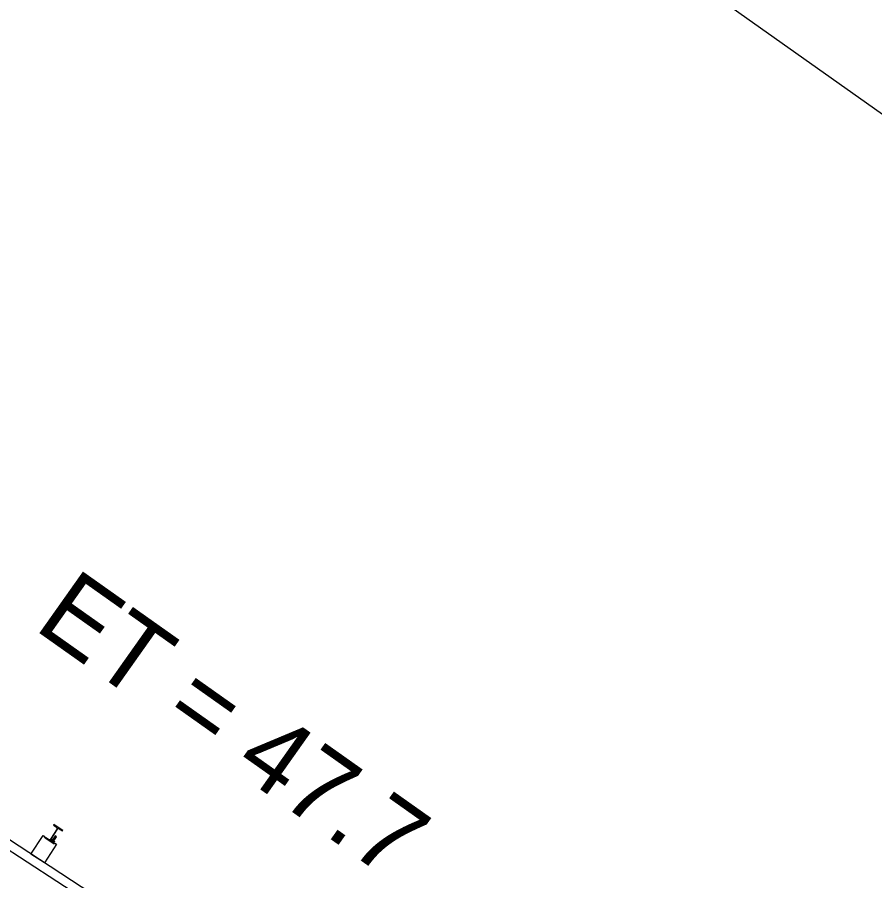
# Model space of a CAD drawing. Extents: x 16457860 to 16462445, y 6896068 to 6900243.
# Drawn here: x 16462375.6 to 16462402.25, y 6897966.79 to 6897993.62 of the extents above; entities that cross this region are included whole.
import ezdxf

# ---------------------------------------------------------------- set-up
doc = ezdxf.new("R2010")
doc.units = 0
for name, color, linetype in [('Draft_DNC', 7, 'Continuous'), ('dsnStdLineWork', 7, 'Continuous'), ('dsnStdShading', 7, 'Continuous')]:
    doc.layers.add(name, color=color, linetype=linetype)

msp = doc.modelspace()

# ---------------------------------------------------------------- linework, layer by layer
at = {"layer": 'Draft_DNC'}
msp.add_lwpolyline([(16462202.578, 6898132.041), (16462444.858, 6897960.634), (16462399.398, 6897896.379), (16462157.118, 6898067.786)], close=True, dxfattribs=at)
at = {"layer": 'dsnStdLineWork'}
for p, q in [((16462392.448, 6897956.957), (16462357.89, 6897979.389)), ((16462392.3, 6897956.73), (16462357.742, 6897979.162)), ((16462376.738, 6897968.531), (16462376.729, 6897968.518)), ((16462376.729, 6897968.518), (16462376.828, 6897968.454)), ((16462377.018, 6897968.35), (16462376.738, 6897968.531)), ((16462376.031, 6897967.614), (16462376.41, 6897968.198)), ((16462376.41, 6897968.198), (16462376.462, 6897968.164)), ((16462376.84, 6897968.397), (16462376.636, 6897968.082)), ((16462376.649, 6897968.074), (16462376.853, 6897968.388)), ((16462376.778, 6897968.182), (16462376.696, 6897968.055)), ((16462376.822, 6897968.154), (16462376.778, 6897968.182)), ((16462376.911, 6897968.4), (16462377.009, 6897968.337)), ((16462377.009, 6897968.337), (16462377.018, 6897968.35)), ((16462376.445, 6897968.137), (16462376.462, 6897968.164)), ((16462376.76, 6897967.933), (16462376.445, 6897968.137)), ((16462376.829, 6897967.926), (16462376.45, 6897967.342)), ((16462376.48, 6897968.134), (16462376.471, 6897968.12)), ((16462376.471, 6897968.12), (16462376.751, 6897967.939)), ((16462376.578, 6897968.07), (16462376.48, 6897968.134)), ((16462376.644, 6897968.038), (16462376.665, 6897968.069)), ((16462376.759, 6897967.952), (16462376.661, 6897968.016)), ((16462376.674, 6897968.069), (16462376.665, 6897968.069)), ((16462376.667, 6897968.018), (16462376.69, 6897968.053)), ((16462376.674, 6897968.069), (16462376.756, 6897968.017)), ((16462376.718, 6897967.986), (16462376.74, 6897968.02)), ((16462376.733, 6897967.969), (16462376.743, 6897967.969)), ((16462376.74, 6897968.027), (16462376.822, 6897968.154)), ((16462376.743, 6897967.969), (16462376.765, 6897968.004)), ((16462376.751, 6897967.939), (16462376.759, 6897967.952)), ((16462376.756, 6897968.017), (16462376.761, 6897968.013)), ((16462376.777, 6897967.96), (16462376.76, 6897967.933)), ((16462376.765, 6897968.004), (16462376.761, 6897968.013)), ((16462376.777, 6897967.96), (16462376.829, 6897967.926)), ((16462376.45, 6897967.342), (16462376.031, 6897967.614))]:
    msp.add_line(p, q, dxfattribs=at)
for centre, start, end in [((16462376.805, 6897968.419), 327.0057, 57.0148), ((16462376.888, 6897968.365), 57.0196, 147.0086), ((16462376.601, 6897968.105), 237.0196, 327.0086), ((16462376.684, 6897968.051), 147.0057, 237.0148)]:
    msp.add_arc(centre, 0.0417, start, end, dxfattribs=at)
for points in [[(16462376.656, 6897968.02), (16462376.657, 6897968.02), (16462376.661, 6897968.018), (16462376.665, 6897968.018), (16462376.667, 6897968.018)], [(16462376.69, 6897968.053), (16462376.688, 6897968.056), (16462376.686, 6897968.061), (16462376.68, 6897968.066), (16462376.672, 6897968.069), (16462376.667, 6897968.069), (16462376.665, 6897968.069)], [(16462376.667, 6897968.018), (16462376.671, 6897968.014), (16462376.678, 6897968.006), (16462376.691, 6897967.996), (16462376.704, 6897967.99), (16462376.713, 6897967.987), (16462376.718, 6897967.986)], [(16462376.74, 6897968.02), (16462376.737, 6897968.024), (16462376.729, 6897968.033), (16462376.717, 6897968.042), (16462376.703, 6897968.049), (16462376.694, 6897968.052), (16462376.69, 6897968.053)], [(16462376.718, 6897967.986), (16462376.718, 6897967.984), (16462376.72, 6897967.98), (16462376.724, 6897967.975), (16462376.731, 6897967.971), (16462376.737, 6897967.969), (16462376.741, 6897967.969), (16462376.743, 6897967.969)], [(16462376.765, 6897968.004), (16462376.765, 6897968.006), (16462376.763, 6897968.009), (16462376.759, 6897968.014), (16462376.753, 6897968.019), (16462376.746, 6897968.02), (16462376.742, 6897968.02), (16462376.74, 6897968.02)]]:
    msp.add_open_spline(points, degree=3, dxfattribs=at)
at = {"layer": 'dsnStdShading'}
for p, q in [((16462376.738, 6897968.531), (16462376.729, 6897968.518)), ((16462376.738, 6897968.531), (16462376.729, 6897968.518)), ((16462376.729, 6897968.518), (16462376.828, 6897968.454)), ((16462376.729, 6897968.518), (16462376.828, 6897968.454)), ((16462377.018, 6897968.35), (16462376.738, 6897968.531)), ((16462377.018, 6897968.35), (16462376.738, 6897968.531)), ((16462376.031, 6897967.614), (16462376.41, 6897968.198)), ((16462376.41, 6897968.198), (16462376.462, 6897968.164)), ((16462376.84, 6897968.397), (16462376.636, 6897968.082)), ((16462376.84, 6897968.397), (16462376.636, 6897968.082)), ((16462376.649, 6897968.074), (16462376.853, 6897968.388)), ((16462376.649, 6897968.074), (16462376.853, 6897968.388)), ((16462376.778, 6897968.182), (16462376.696, 6897968.055)), ((16462376.822, 6897968.154), (16462376.778, 6897968.182)), ((16462376.911, 6897968.4), (16462377.009, 6897968.337)), ((16462376.911, 6897968.4), (16462377.009, 6897968.337)), ((16462377.009, 6897968.337), (16462377.018, 6897968.35)), ((16462377.009, 6897968.337), (16462377.018, 6897968.35)), ((16462376.445, 6897968.137), (16462376.462, 6897968.164)), ((16462376.76, 6897967.933), (16462376.445, 6897968.137)), ((16462376.829, 6897967.926), (16462376.45, 6897967.342)), ((16462376.48, 6897968.134), (16462376.471, 6897968.12)), ((16462376.48, 6897968.134), (16462376.471, 6897968.12)), ((16462376.471, 6897968.12), (16462376.751, 6897967.939)), ((16462376.471, 6897968.12), (16462376.751, 6897967.939)), ((16462376.578, 6897968.07), (16462376.48, 6897968.134)), ((16462376.578, 6897968.07), (16462376.48, 6897968.134)), ((16462376.665, 6897968.069), (16462376.644, 6897968.038)), ((16462376.644, 6897968.038), (16462376.665, 6897968.069)), ((16462376.759, 6897967.952), (16462376.661, 6897968.016)), ((16462376.759, 6897967.952), (16462376.661, 6897968.016)), ((16462376.674, 6897968.069), (16462376.665, 6897968.069)), ((16462376.667, 6897968.018), (16462376.69, 6897968.053)), ((16462376.69, 6897968.053), (16462376.667, 6897968.018)), ((16462376.667, 6897968.018), (16462376.69, 6897968.053)), ((16462376.674, 6897968.069), (16462376.756, 6897968.017)), ((16462376.718, 6897967.986), (16462376.74, 6897968.02)), ((16462376.74, 6897968.02), (16462376.718, 6897967.986)), ((16462376.718, 6897967.986), (16462376.74, 6897968.02)), ((16462376.733, 6897967.969), (16462376.743, 6897967.969)), ((16462376.733, 6897967.969), (16462376.743, 6897967.969)), ((16462376.74, 6897968.027), (16462376.822, 6897968.154)), ((16462376.743, 6897967.969), (16462376.765, 6897968.004)), ((16462376.743, 6897967.969), (16462376.765, 6897968.004)), ((16462376.751, 6897967.939), (16462376.759, 6897967.952)), ((16462376.751, 6897967.939), (16462376.759, 6897967.952)), ((16462376.756, 6897968.017), (16462376.761, 6897968.013)), ((16462376.777, 6897967.96), (16462376.76, 6897967.933)), ((16462376.765, 6897968.004), (16462376.761, 6897968.013)), ((16462376.777, 6897967.96), (16462376.829, 6897967.926)), ((16462376.45, 6897967.342), (16462376.031, 6897967.614))]:
    msp.add_line(p, q, dxfattribs=at)
msp.add_lwpolyline([(16462376.74, 6897968.027), (16462376.822, 6897968.154), (16462376.778, 6897968.182), (16462376.696, 6897968.055)], close=True, dxfattribs=at)
for points in [[(16462376.644, 6897968.038), (16462376.644, 6897968.038)], [(16462376.661, 6897968.016), (16462376.733, 6897967.969), (16462376.733, 6897967.969)], [(16462376.765, 6897968.004), (16462376.761, 6897968.013), (16462376.756, 6897968.017), (16462376.674, 6897968.069), (16462376.665, 6897968.069)]]:
    msp.add_lwpolyline(points, dxfattribs=at)
for centre, start, end in [((16462376.805, 6897968.419), 327.0057, 57.0148), ((16462376.805, 6897968.419), 327.0057, 57.0148), ((16462376.888, 6897968.365), 57.0196, 147.0086), ((16462376.888, 6897968.365), 57.0196, 147.0086), ((16462376.601, 6897968.105), 237.0196, 327.0086), ((16462376.601, 6897968.105), 237.0196, 327.0086), ((16462376.684, 6897968.051), 147.0057, 237.0148), ((16462376.684, 6897968.051), 147.0057, 237.0148), ((16462376.684, 6897968.051), 197.8989, 237.0148)]:
    msp.add_arc(centre, 0.0417, start, end, dxfattribs=at)
for points in [[(16462376.656, 6897968.02), (16462376.657, 6897968.02), (16462376.661, 6897968.018), (16462376.665, 6897968.018), (16462376.667, 6897968.018)], [(16462376.69, 6897968.053), (16462376.688, 6897968.056), (16462376.686, 6897968.061), (16462376.68, 6897968.066), (16462376.672, 6897968.069), (16462376.667, 6897968.069), (16462376.665, 6897968.069)], [(16462376.665, 6897968.069), (16462376.667, 6897968.069), (16462376.672, 6897968.069), (16462376.68, 6897968.066), (16462376.686, 6897968.061), (16462376.688, 6897968.056), (16462376.69, 6897968.053)], [(16462376.69, 6897968.053), (16462376.688, 6897968.056), (16462376.686, 6897968.061), (16462376.68, 6897968.066), (16462376.672, 6897968.069), (16462376.667, 6897968.069), (16462376.665, 6897968.069)], [(16462376.718, 6897967.986), (16462376.713, 6897967.987), (16462376.704, 6897967.99), (16462376.691, 6897967.996), (16462376.678, 6897968.006), (16462376.671, 6897968.014), (16462376.667, 6897968.018)], [(16462376.667, 6897968.018), (16462376.671, 6897968.014), (16462376.678, 6897968.006), (16462376.691, 6897967.996), (16462376.704, 6897967.99), (16462376.713, 6897967.987), (16462376.718, 6897967.986)], [(16462376.667, 6897968.018), (16462376.671, 6897968.014), (16462376.678, 6897968.006), (16462376.691, 6897967.996), (16462376.704, 6897967.99), (16462376.713, 6897967.987), (16462376.718, 6897967.986)], [(16462376.74, 6897968.02), (16462376.737, 6897968.024), (16462376.729, 6897968.033), (16462376.717, 6897968.042), (16462376.703, 6897968.049), (16462376.694, 6897968.052), (16462376.69, 6897968.053)], [(16462376.69, 6897968.053), (16462376.694, 6897968.052), (16462376.703, 6897968.049), (16462376.717, 6897968.042), (16462376.729, 6897968.033), (16462376.737, 6897968.024), (16462376.74, 6897968.02)], [(16462376.74, 6897968.02), (16462376.737, 6897968.024), (16462376.729, 6897968.033), (16462376.717, 6897968.042), (16462376.703, 6897968.049), (16462376.694, 6897968.052), (16462376.69, 6897968.053)], [(16462376.743, 6897967.969), (16462376.741, 6897967.969), (16462376.737, 6897967.969), (16462376.731, 6897967.971), (16462376.724, 6897967.975), (16462376.72, 6897967.98), (16462376.718, 6897967.984), (16462376.718, 6897967.986)], [(16462376.718, 6897967.986), (16462376.718, 6897967.984), (16462376.72, 6897967.98), (16462376.724, 6897967.975), (16462376.731, 6897967.971), (16462376.737, 6897967.969), (16462376.741, 6897967.969), (16462376.743, 6897967.969)], [(16462376.718, 6897967.986), (16462376.718, 6897967.984), (16462376.72, 6897967.98), (16462376.724, 6897967.975), (16462376.731, 6897967.971), (16462376.737, 6897967.969), (16462376.741, 6897967.969), (16462376.743, 6897967.969)], [(16462376.765, 6897968.004), (16462376.765, 6897968.006), (16462376.763, 6897968.009), (16462376.759, 6897968.014), (16462376.753, 6897968.019), (16462376.746, 6897968.02), (16462376.742, 6897968.02), (16462376.74, 6897968.02)], [(16462376.74, 6897968.02), (16462376.742, 6897968.02), (16462376.746, 6897968.02), (16462376.753, 6897968.019), (16462376.759, 6897968.014), (16462376.763, 6897968.009), (16462376.765, 6897968.006), (16462376.765, 6897968.004)], [(16462376.765, 6897968.004), (16462376.765, 6897968.006), (16462376.763, 6897968.009), (16462376.759, 6897968.014), (16462376.753, 6897968.019), (16462376.746, 6897968.02), (16462376.742, 6897968.02), (16462376.74, 6897968.02)]]:
    msp.add_open_spline(points, degree=3, dxfattribs=at)

# ---------------------------------------------------------------- texts
at = {"layer": 'Draft_DNC'}
msp.add_text('ET = 47.7', height=2.3437, rotation=324.7216, dxfattribs=at).set_placement((16462376.082, 6897974.63))

doc.saveas('drawing.dxf')
